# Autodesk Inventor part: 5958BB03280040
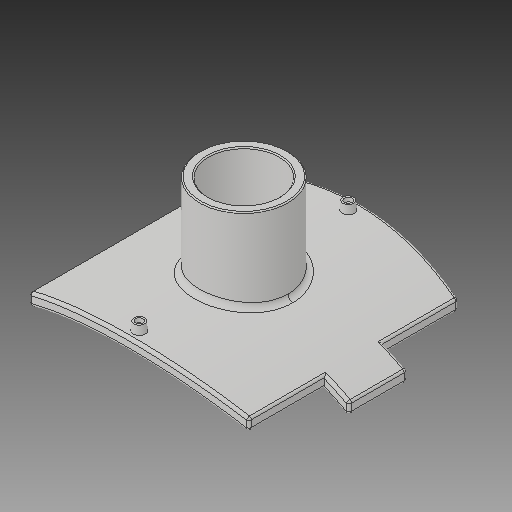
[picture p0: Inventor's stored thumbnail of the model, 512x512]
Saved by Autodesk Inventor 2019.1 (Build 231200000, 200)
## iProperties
Created: 2017-10
Part Number: 5958BB03280040
Material: Generic
Description: PLASSON BRANCH SADDLE 18''-28''IPS x 16''-24''DIPS
Document SubType Name: Modeling
Designer: KIM
Density: 1 g/cm^3
Appearance: Default
Author: KIM
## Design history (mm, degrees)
derived "5958B-1.ipt"
feature "Solid1::5958B-1.ipt"
tag "TaggingFeature1"
body "Solid1"
other parameters: "d0" = 708, "d1" = 14.986, "d2" = 283.464, "d3" = 299.974, "d4" = 0, "d5" = 314.96, "d6" = 74.9935, "d7" = 0, "d8" = 134.9883, "d10" = 0, "d11" = 3.54, "d12" = 379.6, "d13" = 14, "d14" = 134.9883, "d16" = 5 deg, "d18" = 4, "d19" = 14, "d20" = 0, "d21" = 3, "d22" = 0, "d23" = 473.888, "d24" = 114.1, "d25" = 16, "d26" = 91.28, "d28" = 0, "d29" = 9.6, "d31" = 0, "d32" = 83.9216, "d33" = 0, "d34" = 7.08, "d35" = 1.416, "d_" = 708, "d_1" = 114.1, "B_" = 314.96, "H_" = 119.888, "L_" = 299.974, "x_" = 14.986, "D_" = 16, "H1" = 104.902
